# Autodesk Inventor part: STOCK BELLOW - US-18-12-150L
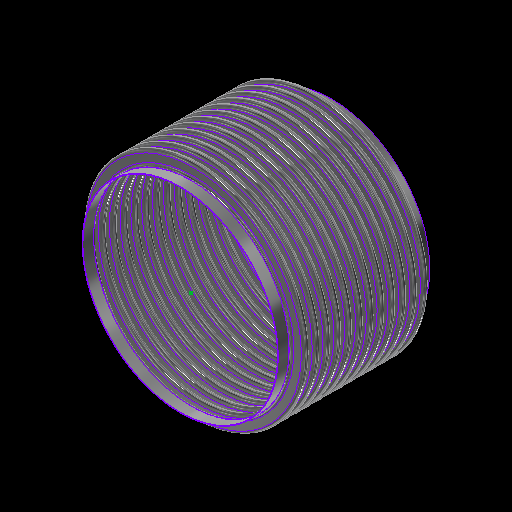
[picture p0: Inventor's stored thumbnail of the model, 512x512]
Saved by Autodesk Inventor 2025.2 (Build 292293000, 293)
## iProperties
Category: 16 GA (0.060 THICK)
RuleStatus: InUse
Created: 2024-01
Part Number: STOCK BELLOW - US-18-12-150L
Project: =STOCK BELLOWS: <Stock Number><SFILL>
Material: ASTM A240-304
Description: =STOCK BELLOWS: <Stock Number>, <SID_> I.D., <SOD_> O.D., <SPLY_> PLY, <Category>, <SNET_CONS> CONS.<PITCH_><STANGENT_> TANGENT<SFILL>
Document SubType Name: Sheet Metal
Designer: GS
Stock Number: U.S-18-12-150L
Surface Area: 29227.1 cm^2
Volume: 2217.06 cm^3
Sheet Metal Rule: Default
Appearance: STAINLESS STEEL
Mass: 17863.5 g
Density: 8.05729 g/cm^3
THK: 0.036
ID: 3.500
OD: 4.250
CONS_: 2
PITCH: 0.500
TANGENT: 0.500
BELLOWS_UPSET: 0.000
d79: 1.000
d82: 1.000
d83: 26.000
d84: 24.000
d174: 8
d214: 8
STHK_: 0.060
SID_: 18.000
SOD_: 20.500
SPITCH_: 1.000
STANGENT__: 1.000
SBELLOWS_UPSET_: 0.000
SDIFF_TAN: 1.000
d252: 2
d275: 2
d287: 0.050
d289: 0.500
d290: 0.000
SOD_NECK: 18 1/8
PLY: 1
PSET: 4.178
PBAR: 1.035
COUNTER: 1.500
NET_TUBE: 3.071
CONS: 2
S_CONS: 0
NET_CONS: 2
ID_M: 88.90 mm
OD_M: 107.95 mm
THK_M: 0.91 mm
ID_U: 3.500 in
OD_U: 4.250 in
THK_U: 0.036 in
TANGENT2: 0.500
TAN_TO_TAN: 1.000 in
d80: 2.571
d81: 10
SID: 2.375
SCONS_: 12
SPITCH: 0.250
STANGENT_: 1.000
SBELLOWS_UPSET: 0.000
SNET_CONS: 12
SS_CONS: 0
SCONS: 8
d190: 8
d191: 1
d192: 1
d193: 8
d194: 0
SIZE: 18.00
PRESSURE: 150
d230: 8
STANGENT: 4.000
SPLY_: 1
d233: 8
d234: 0
d263: 2
d265: 1
d268: 2
d269: 0
d286: 2
d288: 1
d291: 2
d292: 0
SREROLL: 0.750
BLETP: 1.000 ul
PRES_Copy: 85
MATTABLE: 20 GA (0.036 THICK)
PART_NUMBER: U.S-18-12-150L
PITCH_: =, <SPITCH_> PITCH,
CFILL: .
SFILL: .
MESH: ,
COMP: 2.26
EXT: 1.13
LAT: 0.47
ANG: 573
ASR: 3368
LSR: 11701
ANSR: 2451
PRES: 150
COMPM: 22.6
EXTM: 11.3
LATM: 4.70
ASRM: 589.838
PRESM: 10.342
LSRM: 2049.196
ANSRM: 429.244
TEMPMIN: 20
TEMPMAX: 800
TEMPMINM: -7
TEMPMAXM: 427
WEIGHTM: 17.864
WEIGHT: 39.382
Author: GS
Keywords: 20 GA (0.036 THICK)
Comments: =STOCK BELLOW - <STOCK NUMBER>
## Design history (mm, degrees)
sketch "Sketch2"
  geometry: L1 (0, -177.245)-(0, 562.856) reference; L2 (45.364, 0)-(44.45, 0); L3 (48.082, -2.718)-(50.343, -2.718); L4 (48.082, -3.632)-(50.343, -3.632); L5 (50.343, -9.982)-(48.082, -9.982); L6 (50.343, -9.068)-(48.082, -9.068); L7 (45.364, -12.7)-(44.45, -12.7); L8 (48.082, 0)-(48.082, -12.7); L9 (50.343, -6.35)-(53.975, -6.35); L10 (44.45, 0)-(44.45, -12.7); L11 (20.376, 102.841)-(20.376, 101.926); L12 (58.262, 457.127)-(58.262, 349.177); L13 (58.262, 444.427)-(58.262, 336.477); L14 (93.133, -58.817)-(93.133, -71.517); L15 (118.746, -66.401)-(118.746, -66.401); L16 (50.343, -9.068)-(50.343, -9.982); L17 (48.082, -9.068)-(48.082, -9.982); L18 (48.082, -9.525)-(50.343, -9.525); L19 (53.975, 0)-(53.975, -12.7); L20 (-50.343, -9.068)-(-50.343, -9.982); L21 (-50.343, -2.718)-(-48.082, -2.718); L22 (-50.343, -3.632)-(-48.082, -3.632); L23 (-48.082, -9.068)-(-50.343, -9.068); L24 (-50.343, -9.525)-(-48.082, -9.525); L25 (-48.082, -9.982)-(-50.343, -9.982); L26 (-48.082, -9.068)-(-48.082, -9.982); L27 (-44.45, 0.653)-(-44.45, -12.047); L28 (-48.082, -6.35)-(-44.45, -6.35); L29 (-50.343, 0.653)-(-50.343, -12.7); L30 (-53.061, 0)-(-53.975, 0); L31 (-53.975, 0)-(-53.975, -12.7); L32 (-53.061, -12.7)-(-53.975, -12.7); A1 r 2.718 centre (48.082, 0) between (45.364, 0) and (48.082, -2.718); A2 r 3.632 centre (48.082, 0) between (44.45, 0) and (48.082, -3.632); A3 r 3.632 centre (50.343, -6.35) between (50.343, -9.982) and (50.343, -2.718); A4 r 2.718 centre (50.343, -6.35) between (50.343, -9.068) and (50.343, -3.632); A5 r 2.718 centre (48.082, -12.7) between (48.082, -9.982) and (45.364, -12.7); A6 r 3.632 centre (48.082, -12.7) between (48.082, -9.068) and (44.45, -12.7); A7 r 3.175 centre (50.343, -6.35) between (50.343, -9.525) and (53.518, -6.35); A8 r 3.175 centre (48.082, -12.7) between (48.082, -9.525) and (44.907, -12.7); A9 r 2.718 centre (-50.343, -12.7) between (-50.343, -9.982) and (-53.061, -12.7); A10 r 2.718 centre (-48.082, -6.35) between (-48.082, -9.068) and (-48.082, -3.632); A11 r 3.175 centre (-48.082, -6.35) between (-48.082, -9.525) and (-44.907, -6.35); A12 r 3.632 centre (-48.082, -6.35) between (-48.082, -9.982) and (-48.082, -2.718); A13 r 3.175 centre (-50.343, -12.7) between (-50.343, -9.525) and (-53.518, -12.7); A14 r 3.632 centre (-50.343, -12.7) between (-50.343, -9.068) and (-53.975, -12.7); A15 r 2.718 centre (-50.343, 0) between (-53.061, 0) and (-50.343, -2.718); A16 r 3.632 centre (-50.343, 0) between (-53.975, 0) and (-50.343, -3.632); 10 further points
  constraints: 62 end point, 38 point on circle, 20 tangent, 16 centre point, 12 parallel, 9 midpoint, 7 vertical, 6 coincident, 6 concentric, 6 point on line, 4 equal radius, 4 perpendicular, 3 horizontal, 1 collinear, 1 horizontal alignment, 10 other
  dimensions: "THK" = 0.9144 distance of L11.start L11.end; "ID" = 88.9 distance of L11.end point (20.376, 13.026); "OD" = 107.95 distance of L12.start L12.end; "PITCH" = 12.7 distance of L12.start L13.start; "TANGENT" = 12.7 distance of L14.start L14.end; "BELLOWS_UPSET" = 0 distance of L15.start L15.end; "d43" = 88.9 diameter of L10 L1 (= ID); "d44" = 107.95 diameter of L9.end L1 (= OD); "d45" = 0.9144 distance between parallel lines of L5 L6 (computed from THK, PLY); "d46" = 3.6322 radius of A3 (computed from PITCH, THK, PLY); "UPSET_PITCH" = 12.7 distance of L2.end L7.end (derived); "SIDEWALL_ANGLE" = 360 deg dimension on L3 L9 (derived); "CON_GAP" = 5.4356 distance of point (48.082, -9.068) point (48.082, -3.632) (derived); "TAN1" = 4.98728 dimension on A8 (derived); "TAN2" = 4.98728 dimension on A7 (derived); "LEG1" = 2.2606 distance of L18.start L18.end (derived); "d278" = 0.9144 distance between parallel lines of L25 L23 (derived); "d279" = 3.6322 radius of A12 (derived); "d280" = 12.7 distance of L30.end L31.end (derived); "d281" = 360 deg dimension on L21 L28 (derived); "d282" = 5.4356 distance of point (-50.343, -9.068) point (-50.343, -3.632) (derived); "d283" = 4.98728 dimension on A13 (derived); "d284" = 4.98728 dimension on A11 (derived); "d285" = 2.2606 distance of L24.start L24.end (derived); "d293" = 88.9 diameter of L27 L1 (derived); "d294" = 107.95 diameter of L31 L1 (derived)
  node "Sketch Rectangular Pattern1" dims "d31" = 25.4, "ID" = 88.9
  node "Sketch Rectangular Pattern2" dims "d39" = 25.4, "PITCH" = 12.7
revolve "CONS" stored, may be unused: angle "d48" = 90 deg
node "BELLOW MIDPLANE"
pattern_linear "Rectangular Pattern2" dims "d52" = 12.7 (= UPSET_PITCH)
sketch "Sketch5"
  geometry: C1 r 45.364 at (0, 0) reference; C2 r 44.45 at (0, 0) reference
extrude "TANGENT" new body sketch "Sketch5" distance "d53" = 12.7 (= TANGENT); taper "d54" = 0 deg
revolve "SAMETAN" stored, may be unused: angle "d65" = 90 deg
revolve "DIFFTAN" stored, may be unused: angle "d70" = 90 deg
sketch "Sketch9"
  geometry: L1 (53.319, 0)-(-53.319, 0) reference; L2 (0, -17.78)-(0, 17.78) reference; L3 (38.085, 0)-(-38.085, 0); L4 (38.085, -11.906)-(38.085, 11.906); L5 (25.385, -11.906)-(25.385, 11.906); L6 (13.15, 11.906)-(13.15, -11.906); L7 (-25.385, -11.906)-(-25.385, 11.906); L8 (-38.085, -11.906)-(-38.085, 11.906); L9 (37.291, -11.906)-(37.291, 11.906); L10 (38.085, -11.906)-(37.291, -11.906); L11 (38.085, 11.906)-(37.291, 11.906); L12 (13.546, 11.906)-(12.753, 11.906); L13 (12.753, 11.906)-(12.753, -11.906); L14 (12.753, -11.906)-(13.546, -11.906); L15 (13.546, -11.906)-(13.546, 11.906); L16 (-13.546, 11.906)-(-13.546, -11.906); L17 (-13.15, 11.906)-(-13.15, -11.906); L18 (-13.546, -11.906)-(-12.753, -11.906); L19 (-12.753, -11.906)-(-12.753, 11.906); L20 (-12.753, 11.906)-(-13.546, 11.906); L21 (-38.085, -11.906)-(-37.291, -11.906); L22 (-37.291, -11.906)-(-37.291, 11.906); L23 (-37.291, 11.906)-(-38.085, 11.906); L24 (-38.085, 11.906)-(-38.085, -11.906); L25 (38.085, -0.397)-(-38.085, -0.397); L26 (-38.085, -0.397)-(-38.085, 0.397); L27 (-38.085, 0.397)-(38.085, 0.397); L28 (38.085, 0.397)-(38.085, -0.397); L29 (-38.085, 11.906)-(38.085, 11.906); L30 (38.085, 11.906)-(38.085, 12.7); L31 (38.085, 12.7)-(-38.085, 12.7); L32 (-38.085, 12.7)-(-38.085, 11.906); L33 (38.085, -11.906)-(-38.085, -11.906); L34 (-38.085, -11.906)-(-38.085, -12.7); L35 (-38.085, -12.7)-(38.085, -12.7); L36 (38.085, -12.7)-(38.085, -11.906); 30 further points
  constraints: 68 end point, 13 midpoint, 13 parallel, 8 horizontal, 7 perpendicular, 6 equal length, 3 point on line, 2 vertical, 14 other
  dimensions: "d115" = 23.8125 distance of L4.start L4.end (derived); "d116" = 12.7 distance between parallel lines of L4 L5 (derived); "d117" = 12.23516 distance between parallel lines of L5 L6 (derived); "d125" = 38.53427 distance between parallel lines of L7 L6 (derived); "d127" = 12.7 distance between parallel lines of L8 L7 (derived); "d128" = 24.93516 distance between parallel lines of L6 L4 (derived); "d130" = 76.16943 distance between parallel lines of L8 L4 (derived); "RULER_THK" = 0.79375 distance between parallel lines of L4 L9; "d135" = 0.79375 distance of L13.end L14.end (derived); "d138" = 26.29911 distance of L13.end L16.end (derived); "d143" = 0.79375 distance of L22.end L8.end (derived); "d144" = 0.79375 distance between parallel lines of L27 L25 (derived)
extrude "RULER" join sketch "Sketch9" distance "d149" = 0.79375 (derived); taper "d150" = 0 deg
extrude "BARS" join sketch "Sketch9" distance "d151" = 0.79375 (derived); taper "d152" = 0 deg
pattern_linear "Rectangular Pattern4" dims "d155" = 26.29911 (derived)
sketch "Sketch13"
  geometry: L1 (93.149, -52.467)-(93.149, -77.867); L2 (230.124, 0)-(228.6, 0); L3 (230.124, -25.4)-(228.6, -25.4); L4 (253.238, -19.812)-(235.712, -19.812); L5 (253.238, -18.288)-(235.712, -18.288); L6 (253.238, -12.7)-(260.35, -12.7); L7 (235.712, -5.588)-(253.238, -5.588); L8 (235.712, 0)-(235.712, -25.4); L9 (228.6, 0)-(228.6, -25.4); L10 (58.254, 24.269)-(58.254, -496.431); L11 (58.254, -1.131)-(58.254, -521.831); L12 (58.254, -51.931)-(58.254, -572.631); L13 (58.254, -77.331)-(58.254, -598.031); L14 (58.254, -102.731)-(58.254, -623.431); L15 (58.254, -128.131)-(58.254, -648.831); L16 (58.254, -153.531)-(58.254, -674.231); L17 (58.254, -26.531)-(58.254, -547.231); L18 (20.376, 103.45)-(20.376, 101.926); L19 (235.712, -7.112)-(253.238, -7.112); L20 (0, -829.767)-(0, 258.986) reference; L21 (-52.07, 0)-(312.42, 0) reference; A1 r 5.588 centre (235.712, 0) between (230.124, 0) and (235.712, -5.588); A2 r 5.588 centre (235.712, -25.4) between (235.712, -19.812) and (230.124, -25.4); A3 r 7.112 centre (235.712, -25.4) between (235.712, -18.288) and (228.6, -25.4); A4 r 5.588 centre (253.238, -12.7) between (253.238, -18.288) and (253.238, -7.112); A5 r 7.112 centre (253.238, -12.7) between (253.238, -19.812) and (253.238, -5.588); A6 r 7.112 centre (235.712, 0) between (228.6, 0) and (235.712, -7.112); 6 further points; 1 other entity
  constraints: 38 end point, 15 point on circle, 9 tangent, 6 centre point, 6 parallel, 5 vertical alignment, 4 point on line, 4 vertical, 3 coincident, 3 concentric, 2 collinear, 2 equal radius, 1 horizontal, 1 perpendicular, 23 other
  dimensions: "SBELLOWS_UPSET_" = 0 distance of point (118.762, -66.401) point (118.762, -66.401); "STOTAL_THK_BELLOW__" = 1.524 distance between parallel lines of L4 L5 (derived); "d224" = 7.112 radius of A5 (derived); "d225" = 25.4 distance of L2.end L3.end (derived); "SSIDEWALL_ANGLE_" = 360 deg dimension on L7 L6 (derived); "SSCON_GAP_" = 11.176 distance of point (235.712, -18.288) point (235.712, -7.112) (derived); "d235" = 457.2 diameter of L9 L20 (derived); "d236" = 520.7 diameter of L6.end L20 (derived)
  node "Sketch Rectangular Pattern4" dims "d228" = 25.4
  node "Sketch Rectangular Pattern5" dims "d229" = 25.4
revolve "SBELLOW" stored, may be unused: angle "d197" = 90 deg
pattern_linear "Rectangular Pattern5" dims "d204" = 25.4 (derived)
revolve "STANGENT" stored, may be unused: angle "d240" = 90 deg
revolve "SSAMETAN" stored, may be unused: angle "d241" = 90 deg
revolve "SDIFFTAN" stored, may be unused: angle "d246" = 90 deg
revolve "INVCON" stored, may be unused: angle "d295" = 90 deg
pattern_linear "Rectangular Pattern6" dims "d298" = 12.7 (derived)
revolve "INVTANGENT" stored, may be unused: angle "d302" = 90 deg
revolve "INVSAMETAN" stored, may be unused: angle "d307" = 90 deg
revolve "INVDIFFTAN" stored, may be unused: angle "d312" = 90 deg
sketch "ID BELLOW MOUNT CALC"
  geometry: L1 (44.45, 0)-(38.1, 0); L2 (38.1, 0)-(38.1, 12.7); L3 (38.1, 12.7)-(44.45, 12.7); L4 (44.45, 12.7)-(44.45, 0); L5 (36.513, 12.7)-(35.598, 12.7); L6 (35.598, 12.7)-(35.598, 0); L7 (35.598, 0)-(36.513, 0); L8 (36.513, 0)-(36.513, 12.7); L9 (0, -2.54)-(0, 15.24) reference; L10 (-8.89, 0)-(53.34, 0) reference; 1 further point
  constraints: 16 end point, 5 parallel, 2 collinear, 2 horizontal, 2 perpendicular
  dimensions: "d314" = 12.7 distance of L5.end L6.end (derived); "d315" = 0.9144 distance of L5.start L5.end (derived); "IG" = 1.5875 distance between parallel lines of L2 L8; "PIPE_OD" = 88.9 diameter of L4 L9; "PIPE_WALL" = 6.35 distance of L2.end L3.end; "ID_MT_BELLOW" = 71.1962 diameter of L6 L9 (derived)
revolve "CFILL" stored, may be unused: angle "d320" = 90 deg
pattern_linear "Rectangular Pattern7" dims "d323" = 12.7 (derived)
revolve "SFILL" stored, may be unused: angle "d324" = 90 deg
pattern_linear "Rectangular Pattern8" dims "d327" = 25.4 (derived)
node "STOCK BELLOW MIDPLANE"
node "BELLOW"
sketch "Sketch6"
  geometry: L1 (-12.7, 45.364)-(0, 45.364); L2 (0, 45.364)-(0, 44.45); L3 (0, 44.45)-(-12.7, 44.45); L4 (-12.7, 44.45)-(-12.7, 45.364); L5 (10.16, 0)-(-60.96, 0) reference; L6 (-38.1, -89.422)-(-38.1, 153.44) reference; 1 further point
  constraints: 8 end point, 2 parallel, 1 horizontal, 1 perpendicular
  dimensions: "d61" = 12.7 distance of L2.end L3.end (derived); "d62" = 0.9144 distance of L1.end L2.end (derived); "d63" = 88.9 diameter of L3 L5 (derived); "d64" = 25.4 distance between parallel lines of L4 L6 (derived)
sketch "Sketch12"
  geometry: 1 further point
sketch "Sketch14"
  geometry: L1 (-25.4, 230.124)-(0, 230.124); L2 (0, 230.124)-(0, 228.6); L3 (0, 228.6)-(-25.4, 228.6); L4 (-25.4, 228.6)-(-25.4, 230.124); L5 (5.08, 0)-(-30.48, 0) reference; L6 (0, -46.025)-(0, 276.149) reference; 1 further point
  constraints: 8 end point, 2 parallel, 1 collinear, 1 horizontal, 1 perpendicular
  dimensions: "d237" = 1.524 distance of L3.end L1.start (derived); "d238" = 457.2 diameter of L3 L5 (derived); "d239" = 25.4 distance of L1.start L1.end (derived); "SOD_NECK" = 460.248 diameter of L1 L5 (derived)
sketch "Sketch15"
  geometry: L1 (-46.025, 0)-(276.149, 0) reference; L2 (228.6, -304.8)-(230.124, -304.8); L3 (230.124, -304.8)-(230.124, -330.2); L4 (230.124, -330.2)-(228.6, -330.2); L5 (228.6, -330.2)-(228.6, -304.8); L6 (0, -398.78)-(0, 81.28) reference; 1 further point
  constraints: 8 end point, 2 parallel, 1 horizontal, 1 perpendicular
  dimensions: "d205" = 25.4 distance of L4.end L2.start (derived); "d206" = 1.524 distance of L3.end L4.end (derived); "d207" = 457.2 diameter of L5 L6 (derived); "d208" = 304.8 distance between parallel lines of L1 L2 (derived)
node "TANGENT_"
node "SAME_TAN"
sketch "Sketch8"
  geometry: L1 (45.364, -25.4)-(44.45, -25.4); L2 (44.45, -25.4)-(44.45, -38.1); L3 (44.45, -38.1)-(45.364, -38.1); L4 (45.364, -38.1)-(45.364, -25.4); L5 (0, -48.26)-(0, 22.86) reference; L6 (-89.422, 0)-(153.44, 0) reference; 1 further point
  constraints: 8 end point, 2 parallel, 1 horizontal, 1 perpendicular
  dimensions: "d66" = 88.9 diameter of L2 L5 (derived); "TOTAL_THK_BELLOW" = 0.9144 distance of L2.end L3.end (derived); "d68" = 25.4 distance between parallel lines of L1 L6 (derived); "d69" = 12.7 distance of L1.end L2.end (derived)
node "DIFF_TAN"
node "Sketch Rectangular Pattern3" dims "d138" = 26.29911 (derived), "d141" = 25.4
node "SBELLOW_"
node "STANGENT_"
node "SSAME_TAN"
sketch "Sketch16"
  geometry: L1 (230.124, -304.8)-(228.6, -304.8); L2 (228.6, -304.8)-(228.6, -330.2); L3 (228.6, -330.2)-(230.124, -330.2); L4 (230.124, -330.2)-(230.124, -304.8); L5 (0, -398.78)-(0, 81.28) reference; L6 (-46.025, 0)-(276.149, 0) reference; 1 further point
  constraints: 8 end point, 2 parallel, 1 horizontal, 1 perpendicular
  dimensions: "SDIFF_TAN" = 25.4 distance of L3.end L1.start; "d243" = 1.524 distance of L2.end L3.end (derived); "d244" = 304.8 distance between parallel lines of L1 L6 (derived); "d245" = 457.2 diameter of L2 L5 (derived)
node "SDIFF_TAN"
body "Solid15"
sketch "Sketch17"
  geometry: L1 (53.975, 12.7)-(53.061, 12.7); L2 (53.061, 12.7)-(53.061, 0); L3 (53.061, 0)-(53.975, 0); L4 (53.975, 0)-(53.975, 12.7); L5 (0, -2.54)-(0, 15.24) reference; L6 (-10.795, 0)-(64.77, 0) reference; 2 further points
  constraints: 8 end point, 2 parallel, 1 horizontal, 1 midpoint, 1 perpendicular, 1 point on line
  dimensions: "INVTANGENT" = 12.7 distance of L3.end L1.start (derived); "d300" = 0.9144 distance of L1.start L1.end (derived); "d301" = 107.95 diameter of L4 L5 (derived)
body "Solid16"
sketch "Sketch18"
  geometry: L1 (53.975, -25.4)-(53.061, -25.4); L2 (53.061, -25.4)-(53.061, -38.1); L3 (53.061, -38.1)-(53.975, -38.1); L4 (53.975, -38.1)-(53.975, -25.4); L5 (-10.795, 0)-(64.77, 0) reference; L6 (0, -48.26)-(0, 22.86) reference; 1 further point
  constraints: 8 end point, 2 parallel, 1 horizontal, 1 perpendicular
  dimensions: "d303" = 25.4 distance between parallel lines of L1 L5 (derived); "d304" = 12.7 distance of L3.end L1.start (derived); "d305" = 0.9144 distance of L2.end L3.end (derived); "d306" = 107.95 diameter of L4 L6 (derived)
body "Solid17"
sketch "Sketch19"
  geometry: L1 (53.975, -25.4)-(53.061, -25.4); L2 (53.061, -25.4)-(53.061, -38.1); L3 (53.061, -38.1)-(53.975, -38.1); L4 (53.975, -38.1)-(53.975, -25.4); L5 (0, -48.26)-(0, 22.86) reference; L6 (-10.795, 0)-(64.77, 0) reference; 1 further point
  constraints: 8 end point, 2 parallel, 1 horizontal, 1 perpendicular
  dimensions: "d308" = 12.7 distance of L1.end L2.end (derived); "d309" = 107.95 diameter of L4 L5 (derived); "d310" = 0.9144 distance of L2.end L3.end (derived); "d311" = 25.4 distance between parallel lines of L1 L6 (derived)
body "Solid18"
body "Solid19"
body "Solid20"
other parameters: "BMPL" = -152.4, "PSET" = 106.1212 (computed from OD, THK, PLY) [user parameter], "PBAR" = 26.29911 (= 0.570796 x PITCH + OD - ID) [user parameter; used in 1 equation term], "COUNTER" = 15 [user parameter], "NET_TUBE" = 77.99823 (computed from CONS_, PBAR, TANGENT) [user parameter], "S_CONS" = 0 [user parameter; used in 1 equation term], "ID_M" = 88.9 (= ID) [user parameter], "OD_M" = 107.95 (= OD) [user parameter], "THK_M" = 0.9144 (= THK) [user parameter], "ID_U" = 88.9 (= ID) [user parameter], "OD_U" = 107.95 (= OD) [user parameter], "THK_U" = 0.9144 (= THK) [user parameter], "D_UNITS" = 0 [user parameter], "TANGENT2" = 12.7 [user parameter], "TAN_TO_TAN" = 25.4 [user parameter], "OD_NECK" = 90.7288 [user parameter], "d79" = 25.4, "d80" = 65.29823 [user parameter], "d82" = 25.4, "d83" = 660.4, "d84" = 609.6, "sa_0" = 4, "FRAME_THK" = 0.79375 [user parameter], "CON_FLAT" = 12.23516 [user parameter], "SID" = 60.325 [user parameter], "SPITCH" = 6.35 [user parameter], "STANGENT_" = 25.4 [user parameter], "SBELLOWS_UPSET" = 0 [user parameter], "SS_CONS" = 0 [user parameter], "STAN_TO_TAN_" = 304.8 [user parameter], "d100" = 1.524 [user parameter], "d191" = 25.4 [user parameter], "d194" = 0 [user parameter], "STANGENT" = 101.6 [user parameter], "d234" = 0 [user parameter], "SUPSET_PITCH_" = 25.4 [user parameter], "d269" = 0 [user parameter], "d287" = 1.27, "d289" = 12.7, "d290" = 0, "d292" = 0 [user parameter], "Thickness" = 3.048 (derived), "KFactor" = 4.4, "BendRadius" = 3.048 (derived), "BendReliefWidth" = 3.048 (derived), "BendReliefDepth" = 1.524 (derived), "CornerReliefSize" = 12.192 (derived), "SeamGap" = 0.00508, "MinimumRemnant" = 6.096 (derived), "TransitionRadius" = 3.048 (derived), "JacobiRadiusSize" = 3.048 (derived), "GapSize" = 3.048 (derived), "SREROLL" = 19.05 [user parameter], "CUR_STK_PITCH" = 25.4 [user parameter], "d328" = -152.4 (derived), "ASR" = 33680 [user parameter], "LSR" = 117010 [user parameter], "ANSR" = 24510 [user parameter], "BLETP" = 1 [user parameter], "ASRM" = 5898.3784 [user parameter], "PRESM" = 103.41975 [user parameter], "LSRM" = 20491.9613 [user parameter], "ANSRM" = 4292.4363 [user parameter], "TEMPMIN" = 2664.83333 [user parameter], "TEMPMAX" = 6998.16667 [user parameter], "TEMPMINM" = 2664.83333 [user parameter], "TEMPMAXM" = 6998.16667 [user parameter], "WEIGHT" = 178.63506 [user parameter], "WEIGHTM" = 0.17864 [user parameter]
